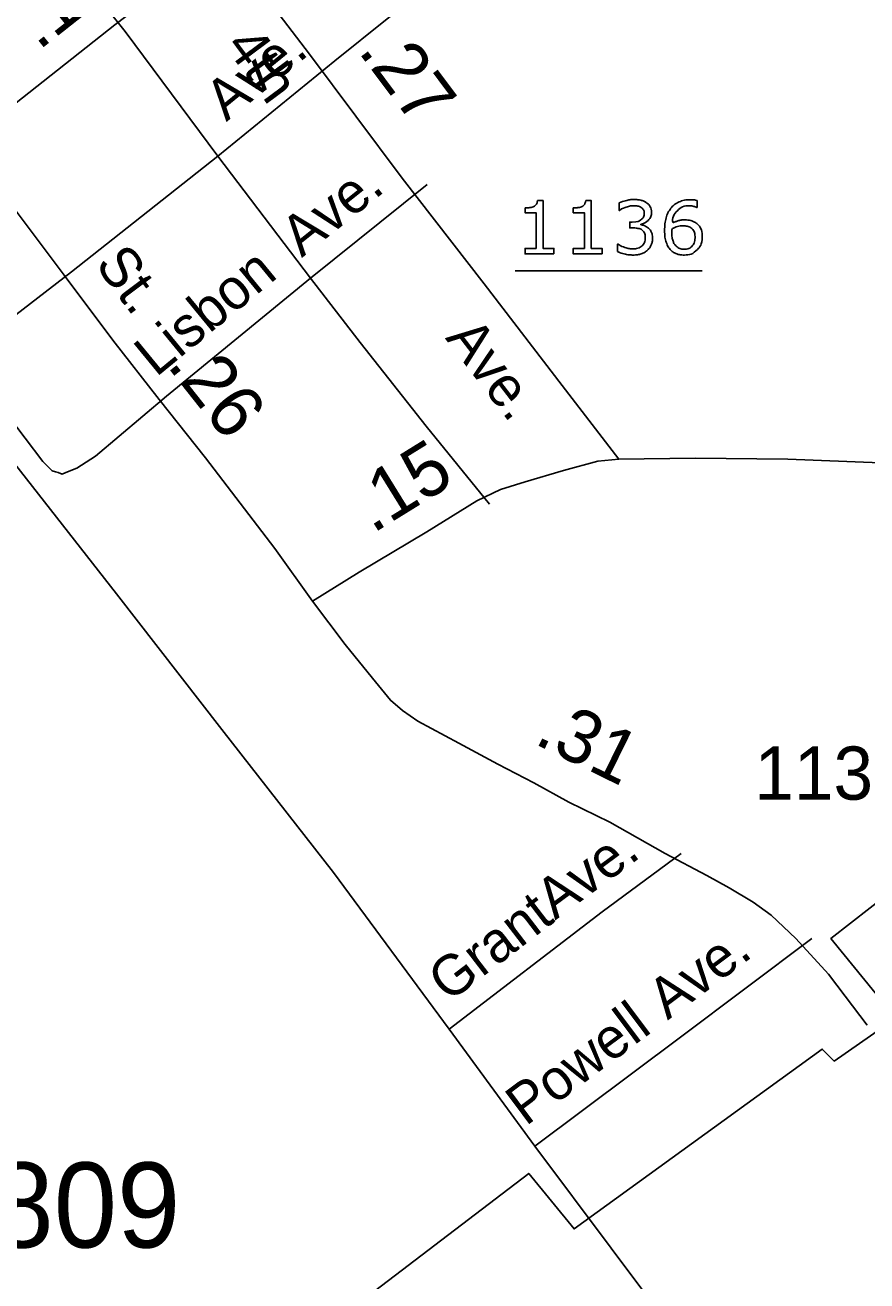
# Model space of a CAD drawing. Extents: x 2093524 to 2270757, y 289120 to 570408.
# Drawn here: x 2182072 to 2184051, y 374863 to 377814 of the extents above; entities that cross this region are included whole.
import ezdxf

# ---------------------------------------------------------------- set-up
doc = ezdxf.new("R2010")
doc.units = 0
for name, color, linetype in [('Exist Boundary Political City Limit New', 7, 'Continuous'), ('Exist Civil Demographics City Population Label', 7, 'Continuous'), ('Exist Road Non-System Type 51', 7, 'Continuous'), ('Exist Road Non-System Type 51 Label', 7, 'Continuous'), ('Exist Road Primary NC Attributed', 7, 'Continuous'), ('Exist Road Primary NC Label', 7, 'Continuous'), ('Exist Road Primary NC Mileage Hundredths English Label', 7, 'Continuous'), ('Exist Road Primary US Attributed', 7, 'Continuous'), ('Exist Road Primary US Mileage Hundredths English Label', 7, 'Continuous'), ('Exist Road Secondary Mileage Hundredths English Label', 7, 'Continuous'), ('Exist Road Secondary Type 51 Attributed', 7, 'Continuous'), ('Exist Road Secondary Type 51 Label', 7, 'Continuous'), ('Exist Road Secondary Type 51 Number Label', 7, 'Continuous'), ('Exist Utilities Telephone Line', 7, 'Continuous'), ('Map Preparation Boundary City Limit Buffer Line', 7, 'Continuous')]:
    doc.layers.add(name, color=color, linetype=linetype)

msp = doc.modelspace()

# ---------------------------------------------------------------- linework, layer by layer
at = {"layer": 'Exist Boundary Political City Limit New'}
msp.add_lwpolyline([(2184724.2, 379372), (2183921.8, 378609.5), (2185353.2, 376748.4), (2183966.2, 375667), (2184118.8, 375479.7), (2183974, 375379), (2183946, 375407.4), (2183362.5, 374984.7), (2183255.8, 375115.3), (2181174.8, 373528.2)], dxfattribs=at)
at = {"layer": 'Exist Road Non-System Type 51'}
for p, q in [((2182094.2, 378067.9), (2182307.6, 377799.1)), ((2182525.4, 377506.4), (2182307.6, 377799.1)), ((2182800, 377729.9), (2182525.4, 377506.4)), ((2182525.4, 377506.4), (2182181, 377234.5)), ((2182742.8, 377219.7), (2182525.4, 377506.4)), ((2182742.8, 377219.7), (2183017.6, 377439.2)), ((2181920.3, 377033.1), (2182181, 377234.5)), ((2182404.6, 376941.9), (2182742.8, 377219.7))]:
    msp.add_line(p, q, dxfattribs=at)
for points in [[(2182847, 378241.9), (2182929.6, 378136.5), (2183010.3, 378028.9), (2183036.3, 377991.2), (2183046.4, 377975.2), (2183046.6, 377955.2), (2183038.7, 377937.1), (2183022.9, 377917), (2183003, 377893), (2182923.3, 377828.6), (2182800, 377729.9)], [(2183163.6, 376688.3), (2183014.7, 376871.4), (2182859.6, 377068.4), (2182742.8, 377219.7)], [(2181920.3, 377033.1), (2182031, 376898), (2182113.6, 376788.3), (2182135.5, 376766.5), (2182143.7, 376764.5), (2182149.7, 376762.6), (2182159.6, 376758.6), (2182167.7, 376762.7), (2182193.4, 376772.8), (2182237.4, 376801.1), (2182404.6, 376941.9)], [(2183614.2, 375867), (2183428.9, 375730.2), (2183068.7, 375454.2)], [(2183921.2, 375667), (2183612.6, 375435.4), (2183270.2, 375179.4)]]:
    msp.add_lwpolyline(points, dxfattribs=at)
at = {"layer": 'Exist Road Primary NC Attributed'}
for points in [[(2182747.7, 376460.2), (2182659.2, 376583.8), (2182496.1, 376796.8), (2182387.4, 376934.1), (2182278.6, 377073.5), (2182163.9, 377226.7), (2181930.6, 377536.4)], [(2183467.9, 376794), (2183418.4, 376788.9), (2183337.6, 376767.2), (2183247.9, 376740.8), (2183189.9, 376722.3), (2183134, 376696.1), (2183016.6, 376623.4), (2182857.1, 376528.6), (2182747.7, 376460.2)], [(2184082.7, 376785), (2183864.7, 376793.7), (2183646.8, 376796.5), (2183467.9, 376794)]]:
    msp.add_lwpolyline(points, dxfattribs=at)
at = {"layer": 'Exist Road Primary US Attributed'}
msp.add_lwpolyline([(2181930.6, 377536.4), (2182282.7, 377814.7), (2182380.3, 377889.1), (2182488.9, 377964), (2182545, 378003)], dxfattribs=at)
at = {"layer": 'Exist Road Secondary Type 51 Attributed'}
for points in [[(2182545, 378003), (2182740.7, 377745.5), (2182958.3, 377454.8), (2183151.5, 377206), (2183334.9, 376967), (2183467.9, 376794)], [(2184051.1, 375463.4), (2184000, 375531.5), (2183960.3, 375583.5), (2183883.8, 375667), (2183825.5, 375722.5), (2183783.3, 375752.4), (2183727.2, 375786.1), (2183674.9, 375815.7), (2183576.8, 375867), (2183446.5, 375940.4), (2183350.2, 375987.7), (2183267.9, 376033.4), (2183183.6, 376076.8), (2183091.4, 376126.3), (2182995.3, 376177.8), (2182959, 376203.5), (2182930.9, 376227.4), (2182888.7, 376279.1), (2182824.3, 376358.7), (2182747.7, 376460.2)]]:
    msp.add_lwpolyline(points, dxfattribs=at)
at = {"layer": 'Exist Road Secondary Type 51 Number Label'}
msp.add_line((2183224, 377236.5), (2183663.9, 377236.5), dxfattribs=at)
for points in [[(2183276.5, 377401.9), (2183289.5, 377401.9), (2183289.5, 377289.2), (2183315.1, 377289.2), (2183315.1, 377276.5)], [(2183389.8, 377401.9), (2183402.8, 377401.9), (2183402.8, 377289.2), (2183428.3, 377289.2), (2183428.3, 377276.5)], [(2183469, 377378.7), (2183468.2, 377378.7), (2183468.2, 377396.2)], [(2183651.7, 377401.9), (2183651.7, 377385.8), (2183650.9, 377385.8)], [(2183315.1, 377276.5), (2183247.4, 377276.5), (2183247.4, 377289.2), (2183273.4, 377289.2), (2183273.4, 377373), (2183247.4, 377373), (2183247.4, 377384.4)], [(2183428.3, 377276.5), (2183360.7, 377276.5), (2183360.7, 377289.2), (2183386.7, 377289.2), (2183386.7, 377373), (2183360.7, 377373), (2183360.7, 377384.4)], [(2183501, 377337.4), (2183493.5, 377337.4), (2183493.5, 377351.3), (2183499.3, 377351.3)], [(2183519.7, 377346), (2183519.7, 377344.8)], [(2183464.6, 377281.7), (2183464.6, 377299.2), (2183465.8, 377299.2)]]:
    msp.add_lwpolyline(points, dxfattribs=at)
for points in [[(2183247.4, 377384.4), (2183252.7, 377384.4), (2183258.7, 377385.3), (2183264.8, 377386.2), (2183267.9, 377387.9), (2183271.7, 377390), (2183274, 377393.2), (2183276.2, 377396.4), (2183276.5, 377401.9)], [(2183360.7, 377384.4), (2183366, 377384.4), (2183372, 377385.3), (2183378.1, 377386.2), (2183381.2, 377387.9), (2183385, 377390), (2183387.3, 377393.2), (2183389.5, 377396.4), (2183389.8, 377401.9)], [(2183468.2, 377396.2), (2183474.1, 377399.2), (2183484.1, 377401.7), (2183494, 377404.1), (2183503.4, 377404.1), (2183512.5, 377404.1), (2183519.5, 377402.5), (2183526.5, 377400.8), (2183532.1, 377397.1), (2183538.2, 377393), (2183541.3, 377387.3), (2183544.4, 377381.6), (2183544.4, 377374), (2183544.4, 377363.6), (2183537, 377355.8), (2183529.7, 377348), (2183519.7, 377346)], [(2183499.3, 377351.3), (2183512.1, 377351.3), (2183519.7, 377356.6), (2183527.3, 377362), (2183527.3, 377372.2), (2183527.3, 377376.8), (2183525.4, 377380.2), (2183523.5, 377383.6), (2183520, 377385.8), (2183516.4, 377388), (2183512.3, 377388.8), (2183508.2, 377389.6), (2183503, 377389.6), (2183495, 377389.6), (2183486, 377386.8), (2183477, 377383.9), (2183469, 377378.7)], [(2183663.9, 377317), (2183663.9, 377297.9), (2183651.3, 377285.9), (2183638.8, 377273.8), (2183620.6, 377273.8), (2183611.3, 377273.8), (2183603.8, 377276.7), (2183596.2, 377279.5), (2183590.4, 377285.2), (2183583.2, 377292.1), (2183579.3, 377303.6), (2183575.4, 377315.1), (2183575.4, 377331.4), (2183575.4, 377348), (2183579, 377360.8), (2183582.6, 377373.7), (2183590.4, 377383.7), (2183597.8, 377393.2), (2183609.4, 377398.5), (2183621.1, 377403.8), (2183636.6, 377403.8), (2183641.6, 377403.8), (2183644.9, 377403.4), (2183648.3, 377403), (2183651.7, 377401.9)], [(2183650.9, 377385.8), (2183648.6, 377387), (2183643.8, 377388.2), (2183639.1, 377389.3), (2183634.1, 377389.3), (2183616.1, 377389.3), (2183605.4, 377378), (2183594.6, 377366.8), (2183592.9, 377347.5), (2183599.9, 377351.8), (2183606.8, 377354), (2183613.6, 377356.3), (2183622.6, 377356.3), (2183630.5, 377356.3), (2183636.6, 377354.8), (2183642.7, 377353.3), (2183649.1, 377348.9), (2183656.4, 377343.8), (2183660.2, 377336), (2183663.9, 377328.1), (2183663.9, 377317)], [(2183537.7, 377336.7), (2183541.7, 377333.1), (2183544.3, 377327.6), (2183546.9, 377322.1), (2183546.9, 377313.5), (2183546.9, 377304.9), (2183543.8, 377297.8), (2183540.7, 377290.6), (2183535.1, 377285.3), (2183528.8, 377279.5), (2183520.3, 377276.6), (2183511.8, 377273.8), (2183501.6, 377273.8), (2183491.2, 377273.8), (2183481.1, 377276.3), (2183471, 377278.8), (2183464.6, 377281.7)], [(2183465.8, 377299.2), (2183473, 377294.5), (2183482.7, 377291.4), (2183492.3, 377288.3), (2183501.3, 377288.3), (2183506.6, 377288.3), (2183512.6, 377290.1), (2183518.5, 377291.9), (2183522.2, 377295.3), (2183526.1, 377299), (2183528, 377303.5), (2183529.9, 377307.9), (2183529.9, 377314.7), (2183529.9, 377321.5), (2183527.7, 377325.9), (2183525.6, 377330.3), (2183521.8, 377332.9), (2183518, 377335.5), (2183512.6, 377336.4), (2183507.3, 377337.4), (2183501, 377337.4)], [(2183519.7, 377344.8), (2183523.7, 377344.2), (2183528.9, 377342), (2183534.1, 377339.9), (2183537.7, 377336.7)], [(2183646.9, 377316.2), (2183646.9, 377324), (2183644.5, 377329.2), (2183642.2, 377334.3), (2183637, 377338), (2183633.1, 377340.7), (2183628.4, 377341.6), (2183623.7, 377342.4), (2183618.6, 377342.4), (2183611.5, 377342.4), (2183605.4, 377340.7), (2183599.2, 377339), (2183592.8, 377335.5), (2183592.6, 377333.7), (2183592.5, 377332), (2183592.5, 377330.2), (2183592.5, 377327.6), (2183592.5, 377314.4), (2183595.2, 377306.7), (2183597.9, 377299.1), (2183602.7, 377294.6), (2183606.5, 377290.9), (2183611, 377289.2), (2183615.5, 377287.5), (2183620.8, 377287.5), (2183632.9, 377287.5), (2183639.9, 377294.9), (2183646.9, 377302.3), (2183646.9, 377316.2)]]:
    msp.add_open_spline(points, degree=3, dxfattribs=at)
at = {"layer": 'Exist Utilities Telephone Line'}
msp.add_line((2183068.7, 375454.2), (2183270.2, 375179.4), dxfattribs=at)
for points in [[(2181878.4, 376999), (2182033.5, 376801.9), (2182287.2, 376477.5), (2182534.8, 376158.9), (2182796.7, 375822.5), (2183068.7, 375454.2)], [(2183270.2, 375179.4), (2183628.8, 374699.6), (2184029.6, 374178.1), (2184299.4, 373829.8)]]:
    msp.add_lwpolyline(points, dxfattribs=at)
at = {"layer": 'Map Preparation Boundary City Limit Buffer Line'}
msp.add_lwpolyline([(2184724.2, 379372), (2183921.8, 378609.5), (2185353.2, 376748.4), (2183966.2, 375667), (2184118.8, 375479.7), (2183974, 375379), (2183946, 375407.4), (2183362.5, 374984.7), (2183255.8, 375115.3), (2181174.8, 373528.2)], dxfattribs=at)

# ---------------------------------------------------------------- texts
at = {"layer": 'Exist Civil Demographics City Population Label'}
msp.add_text('pop. 809', height=200, dxfattribs=at).set_placement((2181395.9, 374940.9))
at = {"layer": 'Exist Road Non-System Type 51 Label'}
for s, rotation, p in [('Ave.', 39.1418, (2182545.2, 377586)), ('Ave.', 38.6239, (2182722.5, 377266.5)), ('Lisbon', 39.3959, (2182379.8, 376985.2)), ('Ave.', 36.4555, (2183318.1, 375709.5)), ('Grant', 37.4567, (2183067.3, 375515.1)), ('Ave.', 36.8934, (2183582.5, 375474.3)), ('Powell', 36.7751, (2183248.8, 375224.9))]:
    msp.add_text(s, height=95, rotation=rotation, dxfattribs=at).set_placement(p)
at = {"layer": 'Exist Road Primary NC Label'}
msp.add_text('St.', height=95, rotation=306.8204, dxfattribs=at).set_placement((2182234.7, 377251.1))
at = {"layer": 'Exist Road Primary NC Mileage Hundredths English Label'}
for s, rotation, p in [('.26', 308.3482, (2182403.5, 377014.6)), ('.15', 31.7445, (2182889, 376618))]:
    msp.add_text(s, height=125, rotation=rotation, dxfattribs=at).set_placement(p)
at = {"layer": 'Exist Road Primary US Mileage Hundredths English Label'}
msp.add_text('.15', height=125, rotation=38.3185, dxfattribs=at).set_placement((2182103.7, 377752.9))
at = {"layer": 'Exist Road Secondary Mileage Hundredths English Label'}
for s, rotation, p in [('.27', 306.8167, (2182853.2, 377753)), ('.31', 333.8245, (2183265.5, 376126.9))]:
    msp.add_text(s, height=125, rotation=rotation, dxfattribs=at).set_placement(p)
at = {"layer": 'Exist Road Secondary Type 51 Label'}
for s, rotation, p in [('Church', 37.378, (2181829.6, 377750.9)), ('4th', 306.5672, (2182540, 377764.6)), ('Ave.', 307.5035, (2183058.3, 377078.4))]:
    msp.add_text(s, height=95, rotation=rotation, dxfattribs=at).set_placement(p)
at = {"layer": 'Exist Road Secondary Type 51 Number Label'}
msp.add_text('1133', height=125, dxfattribs=at).set_placement((2183786.4, 375993.6))

doc.saveas('drawing.dxf')
